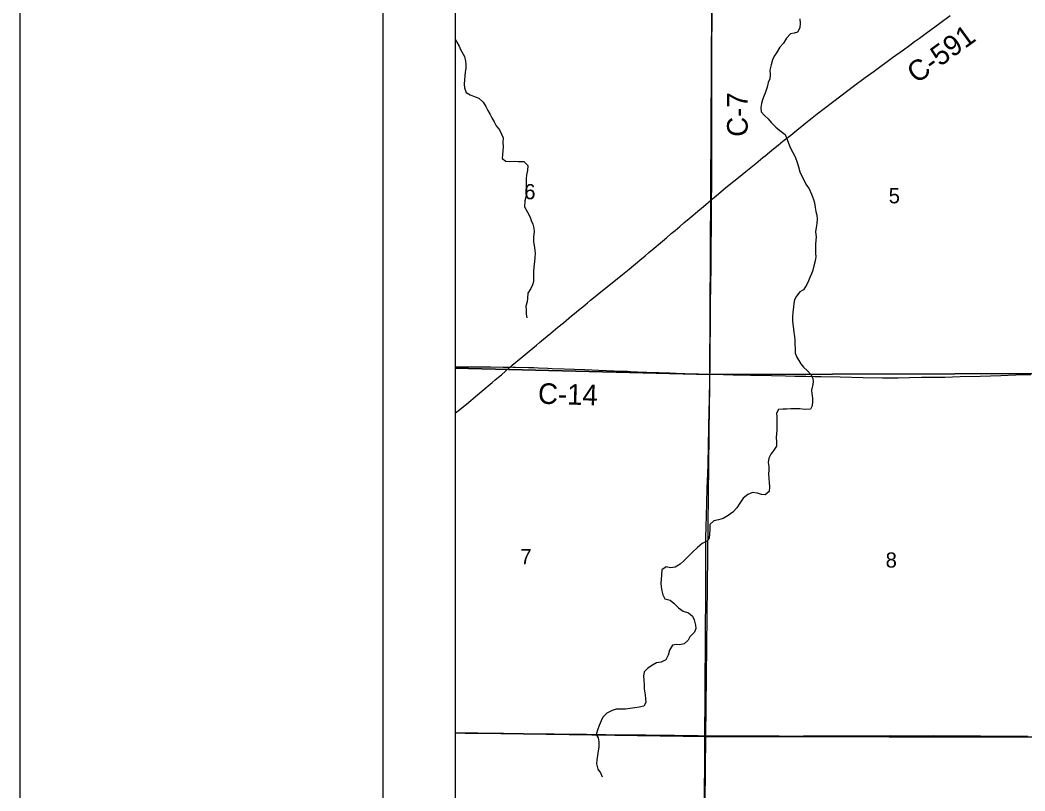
# Model space of a CAD drawing. Extents: x 0 to 34, y 0 to 22.
# Drawn here: x 2 to 3.385, y 16.332 to 17.395 of the extents above; entities that cross this region are included whole.
import ezdxf

# ---------------------------------------------------------------- set-up
doc = ezdxf.new("R2010")
doc.units = 0
for name, color, linetype in [('GM_X_County', 7, 'Continuous'), ('GM_X_County_Road', 7, 'Continuous'), ('GM_X_County_Road_Text', 7, 'Continuous'), ('GM_X_Minor_River', 7, 'Continuous'), ('GM_X_Section', 7, 'Continuous'), ('GM_X_Section_Text', 7, 'Continuous'), ('GM_X_Township', 7, 'Continuous'), ('GM_X_Township_Road', 7, 'Continuous'), ('SH_Border', 7, 'Continuous'), ('SH_Data', 7, 'Continuous')]:
    doc.layers.add(name, color=color, linetype=linetype)

msp = doc.modelspace()

# ---------------------------------------------------------------- linework, layer by layer
at = {"layer": 'GM_X_County'}
msp.add_lwpolyline([(9.4, 14.3965), (9.4, 20.9), (2.6, 20.9), (2.6, 14.4092)], dxfattribs=at)
at = {"layer": 'GM_X_County_Road'}
for points in [[(2.9535, 17.1477), (2.9535, 17.1515), (2.9536, 17.163), (2.9537, 17.1801), (2.9538, 17.1919), (2.9538, 17.2311), (2.9538, 17.264), (2.9538, 17.2836), (2.9539, 17.3181), (2.9539, 17.3355), (2.954, 17.3532), (2.9543, 17.4048), (2.9546, 17.4107), (2.9549, 17.4148)], [(2.9535, 17.1477), (2.9571, 17.1507), (2.963, 17.1558), (2.9699, 17.1616), (2.9756, 17.1663), (2.9841, 17.1732), (2.9882, 17.1765), (2.9955, 17.1823), (3.0006, 17.1864), (3.0074, 17.1918), (3.0146, 17.1977), (3.0242, 17.2056), (3.0271, 17.208), (3.0334, 17.213), (3.0389, 17.2176), (3.0454, 17.2229), (3.0519, 17.2282), (3.0625, 17.2368), (3.071, 17.2436), (3.0807, 17.2514), (3.0836, 17.2538), (3.088, 17.2572), (3.0919, 17.2603), (3.099, 17.2658), (3.1085, 17.2733), (3.1219, 17.2835), (3.1492, 17.304), (3.1654, 17.3162), (3.1774, 17.325), (3.2028, 17.3435), (3.2179, 17.3544), (3.2267, 17.3608), (3.2334, 17.3658), (3.24, 17.3705), (3.2492, 17.3774), (3.2683, 17.3913), (3.2822, 17.4016)], [(2.6762, 16.9169), (2.6787, 16.9192), (2.6911, 16.9296), (2.6992, 16.9364), (2.7071, 16.943), (2.7121, 16.9471), (2.7161, 16.9505), (2.7216, 16.9551), (2.7319, 16.9637), (2.7415, 16.9716), (2.7491, 16.9779), (2.7603, 16.9873), (2.7644, 16.9907), (2.77, 16.9952), (2.7757, 16.9999), (2.7822, 17.0053), (2.7867, 17.009), (2.793, 17.0141), (2.7983, 17.0185), (2.8162, 17.0329), (2.8305, 17.0444), (2.8396, 17.0518), (2.8545, 17.0641), (2.8619, 17.0703), (2.8671, 17.0747), (2.8743, 17.0807), (2.8828, 17.0879), (2.8911, 17.095), (2.8979, 17.1008), (2.9031, 17.1053), (2.9095, 17.1107), (2.9152, 17.1155), (2.9223, 17.1215), (2.928, 17.1263), (2.9347, 17.1319), (2.9395, 17.1359), (2.9457, 17.1411), (2.9514, 17.1459), (2.9535, 17.1477)], [(2.6, 16.8531), (2.6023, 16.855), (2.6153, 16.8657), (2.6305, 16.8785), (2.6365, 16.8835), (2.6511, 16.8956), (2.6551, 16.899), (2.6596, 16.9028), (2.6636, 16.9062), (2.6745, 16.9155), (2.6762, 16.9169)], [(2.6762, 16.9169), (2.6794, 16.9168), (2.683, 16.9168), (2.701, 16.9162), (2.7041, 16.9162), (2.7082, 16.916), (2.7141, 16.9158), (2.7277, 16.9152), (2.7336, 16.9149), (2.7501, 16.9143), (2.7787, 16.9133), (2.7982, 16.9125), (2.8193, 16.9117), (2.8377, 16.911), (2.8417, 16.9108), (2.8513, 16.9104), (2.8641, 16.9099), (2.8805, 16.9094), (2.8954, 16.9088), (2.914, 16.908), (2.9165, 16.9079), (2.9237, 16.9076), (2.9349, 16.9073), (2.9512, 16.9068)], [(2.9512, 16.9068), (2.9535, 16.9068), (2.97, 16.9064), (2.9833, 16.9061), (3.0072, 16.9057), (3.0209, 16.9054), (3.0361, 16.905), (3.0554, 16.9047), (3.0684, 16.9044), (3.0834, 16.9042), (3.0958, 16.9039), (3.1045, 16.9037), (3.1309, 16.9032), (3.1623, 16.9025), (3.189, 16.9021), (3.1983, 16.902), (3.2108, 16.9021), (3.2263, 16.9023), (3.2428, 16.9026), (3.263, 16.9028), (3.2751, 16.903), (3.2962, 16.9037), (3.3239, 16.9043), (3.3381, 16.9046), (3.3524, 16.9051), (3.3729, 16.906), (3.3934, 16.9067)]]:
    msp.add_lwpolyline(points, dxfattribs=at)
at = {"layer": 'GM_X_Minor_River'}
for points in [[(3.0751, 17.397), (3.0755, 17.3913), (3.0751, 17.3846), (3.0721, 17.3786), (3.0672, 17.3774), (3.0621, 17.3765), (3.0566, 17.3702), (3.0526, 17.3636), (3.0477, 17.3579), (3.0428, 17.3503), (3.0398, 17.3456), (3.0375, 17.3404), (3.0354, 17.3334), (3.0339, 17.3264), (3.0341, 17.3203), (3.0337, 17.3141), (3.0316, 17.3092), (3.0299, 17.3027), (3.028, 17.2961), (3.0258, 17.2913), (3.0235, 17.2853), (3.0224, 17.2805), (3.0212, 17.2747), (3.022, 17.269), (3.0263, 17.2635), (3.0316, 17.2589), (3.0354, 17.2542), (3.0418, 17.2476), (3.0477, 17.2432), (3.0547, 17.2373), (3.0577, 17.2307), (3.0594, 17.2256), (3.0621, 17.2187), (3.0653, 17.2125), (3.0685, 17.2066), (3.0715, 17.199), (3.0731, 17.1928), (3.0749, 17.1861), (3.0772, 17.181), (3.081, 17.1742), (3.0836, 17.1689), (3.0878, 17.1626), (3.0912, 17.1552), (3.094, 17.148), (3.0954, 17.1431), (3.0963, 17.1367), (3.0973, 17.1312), (3.0984, 17.1264), (3.0988, 17.1206), (3.0986, 17.1147), (3.0978, 17.1092), (3.0969, 17.1031), (3.0975, 17.0965), (3.0973, 17.0914), (3.0969, 17.0863), (3.0967, 17.0796), (3.0967, 17.0737), (3.0971, 17.069), (3.0961, 17.0631), (3.0944, 17.0563), (3.0931, 17.0504), (3.091, 17.0453), (3.0887, 17.0404), (3.087, 17.0356), (3.0846, 17.0307), (3.0804, 17.0235), (3.0753, 17.0203)], [(2.6, 17.3696), (2.6021, 17.3648), (2.6052, 17.3595), (2.6074, 17.3547), (2.6127, 17.3452), (2.6141, 17.3386), (2.6146, 17.3339), (2.6144, 17.3286), (2.6135, 17.3236), (2.6131, 17.3185), (2.6127, 17.313), (2.6125, 17.3069), (2.6127, 17.3018), (2.615, 17.2954), (2.6207, 17.2922), (2.6273, 17.2893), (2.6326, 17.2876), (2.6386, 17.2819), (2.6422, 17.2761), (2.6451, 17.2704), (2.6481, 17.2653), (2.6504, 17.2603), (2.6538, 17.2552), (2.6562, 17.2497), (2.6608, 17.2438), (2.6636, 17.2381), (2.6659, 17.2327), (2.6657, 17.2266), (2.6661, 17.2205), (2.6657, 17.2148), (2.6651, 17.2099), (2.6647, 17.2044), (2.6697, 17.2006), (2.675, 17.2002), (2.682, 17.2006), (2.6869, 17.2004), (2.6944, 17.2001), (2.7001, 17.1947), (2.6994, 17.1879), (2.6984, 17.1819), (2.6978, 17.1762), (2.6977, 17.1697), (2.6978, 17.165), (2.6982, 17.1593), (2.698, 17.1529), (2.696, 17.1458), (2.6956, 17.1377), (2.6994, 17.1305), (2.7033, 17.1237), (2.7048, 17.1189), (2.7069, 17.114), (2.7082, 17.1083), (2.7086, 17.1036), (2.7079, 17.096), (2.7077, 17.0895), (2.7086, 17.0842), (2.7098, 17.0782), (2.7103, 17.0734), (2.7098, 17.0681), (2.7092, 17.0621), (2.7084, 17.055), (2.7079, 17.048), (2.7079, 17.0423), (2.7077, 17.0349), (2.7065, 17.03), (2.7041, 17.0253), (2.6999, 17.0186), (2.6994, 17.012), (2.6992, 17.0067), (2.6975, 17.0008), (2.6977, 16.9955), (2.698, 16.9896)], [(3.0753, 17.0203), (3.0704, 17.0144), (3.0678, 17.0097), (3.067, 17.0045), (3.0662, 16.9998), (3.0653, 16.9918), (3.0649, 16.9865), (3.0649, 16.981), (3.0655, 16.9761), (3.0662, 16.9693), (3.067, 16.9642), (3.0679, 16.959), (3.0683, 16.9532), (3.0683, 16.9473), (3.0685, 16.9426), (3.0689, 16.9359), (3.0708, 16.9306), (3.0736, 16.9259), (3.0766, 16.9211), (3.0804, 16.9164), (3.0859, 16.9117), (3.0904, 16.9064), (3.0929, 16.9014), (3.0937, 16.8961), (3.0925, 16.891), (3.091, 16.8851), (3.0918, 16.8804), (3.0925, 16.874), (3.0925, 16.8692), (3.092, 16.8635), (3.0899, 16.8586), (3.0821, 16.858), (3.0753, 16.859), (3.0691, 16.8593), (3.0628, 16.8592), (3.0566, 16.8586), (3.0517, 16.8586), (3.0456, 16.8582), (3.043, 16.8533), (3.0432, 16.848), (3.0432, 16.8351), (3.0433, 16.8298), (3.0428, 16.8245), (3.0426, 16.8197), (3.0428, 16.8135), (3.0428, 16.8076), (3.0392, 16.8021), (3.035, 16.7968), (3.0324, 16.7911), (3.0314, 16.7852), (3.0322, 16.7797), (3.0322, 16.7746), (3.0318, 16.7695), (3.0326, 16.763), (3.0328, 16.7577), (3.0333, 16.7517), (3.0329, 16.7452), (3.0275, 16.7405), (3.0222, 16.7412), (3.0169, 16.7429), (3.0099, 16.7439), (3.0032, 16.741), (2.9972, 16.7361), (2.9923, 16.7291), (2.9881, 16.7225), (2.9828, 16.7166), (2.9764, 16.7118), (2.9692, 16.7081), (2.9632, 16.706), (2.9565, 16.7046), (2.9511, 16.6995), (2.9509, 16.6933), (2.9507, 16.6864), (2.9499, 16.6811), (2.9473, 16.6764), (2.9406, 16.6734), (2.9338, 16.668), (2.9272, 16.6614), (2.921, 16.6553), (2.9153, 16.6497), (2.9102, 16.6447), (2.9034, 16.6409), (2.8968, 16.64), (2.8909, 16.6411), (2.8847, 16.6371), (2.8845, 16.6301), (2.8837, 16.6237), (2.8835, 16.6186), (2.8837, 16.6138), (2.8847, 16.6079), (2.886, 16.6024), (2.8888, 16.5969), (2.8964, 16.5954), (2.9015, 16.5909), (2.9076, 16.5848), (2.9144, 16.5803), (2.9215, 16.5776), (2.9272, 16.5731), (2.9293, 16.5681), (2.9312, 16.5609), (2.9316, 16.556)], [(2.698, 16.9896), (2.6988, 16.9847)], [(2.9316, 16.556), (2.9299, 16.5511), (2.9236, 16.5448), (2.9212, 16.5401), (2.9157, 16.5348), (2.9098, 16.5338), (2.9049, 16.534), (2.8994, 16.5333), (2.8954, 16.5262), (2.8934, 16.5192), (2.8903, 16.513), (2.8841, 16.5099), (2.8777, 16.5088), (2.872, 16.5054), (2.8656, 16.5016), (2.8603, 16.4963), (2.8597, 16.4902), (2.8599, 16.4849), (2.8607, 16.4785), (2.8607, 16.4728), (2.8618, 16.4648), (2.8622, 16.4593), (2.8629, 16.454), (2.8599, 16.4489), (2.8537, 16.4477), (2.8476, 16.4468), (2.841, 16.446), (2.8347, 16.4451), (2.827, 16.4447), (2.8219, 16.4447), (2.8162, 16.4432), (2.8088, 16.4394), (2.8035, 16.4341), (2.8013, 16.4288), (2.7984, 16.4223), (2.796, 16.4161), (2.7941, 16.41), (2.7971, 16.4053), (2.7981, 16.3998), (2.7981, 16.3927), (2.7971, 16.3876), (2.796, 16.3808), (2.7952, 16.3751), (2.7947, 16.3694), (2.7964, 16.3622), (2.8001, 16.3573), (2.8026, 16.3514)]]:
    msp.add_lwpolyline(points, dxfattribs=at)
at = {"layer": 'GM_X_Section'}
for p, q in [((2.6, 17.4194), (2.6, 16.9153)), ((2.6, 16.9153), (2.6, 16.4121)), ((2.6, 16.4121), (2.6, 15.9095))]:
    msp.add_line(p, q, dxfattribs=at)
for points in [[(2.6, 16.9153), (2.9508, 16.9064), (2.9539, 17.4153), (2.6, 17.4194)], [(2.6, 16.4121), (2.9456, 16.4074), (2.9508, 16.9064), (2.6, 16.9153)], [(2.6, 15.9095), (2.9405, 15.9076), (2.9456, 16.4074), (2.6, 16.4121)]]:
    msp.add_lwpolyline(points, dxfattribs=at)
for points in [[(2.9539, 17.4153), (2.9558, 17.4152), (3.4597, 17.4098), (3.458, 16.9079), (2.9508, 16.9064)], [(2.9508, 16.9064), (3.458, 16.9079), (3.4505, 16.4063), (2.9456, 16.4074)], [(2.9456, 16.4074), (3.4505, 16.4063), (3.4449, 15.9065), (2.9405, 15.9076)]]:
    msp.add_lwpolyline(points, close=True, dxfattribs=at)
at = {"layer": 'GM_X_Township'}
msp.add_line((2.6, 17.4175), (2.6, 14.4092), dxfattribs=at)
at = {"layer": 'GM_X_Township_Road'}
for points in [[(2.9512, 16.9068), (2.9513, 16.9101), (2.9517, 16.9461), (2.9519, 16.9704), (2.9521, 16.9999), (2.9525, 17.0329), (2.9527, 17.0512), (2.953, 17.0689), (2.953, 17.0885), (2.9531, 17.1034), (2.9532, 17.1177), (2.9533, 17.1407), (2.9535, 17.1477)], [(2.6, 16.9171), (2.6056, 16.9171), (2.6485, 16.9169), (2.6659, 16.9167), (2.6706, 16.9166), (2.673, 16.9167), (2.6762, 16.9169)], [(2.9442, 16.4083), (2.9442, 16.4179), (2.9445, 16.4514), (2.9446, 16.4688), (2.9447, 16.4953), (2.9449, 16.5217), (2.945, 16.544), (2.9452, 16.5627), (2.9453, 16.5904), (2.9454, 16.6059), (2.9455, 16.6155), (2.9456, 16.6292), (2.9455, 16.6503), (2.9455, 16.6637), (2.9457, 16.6802), (2.9459, 16.6973), (2.9463, 16.7112), (2.947, 16.7293), (2.9475, 16.7498), (2.9482, 16.7696), (2.9486, 16.7833), (2.9491, 16.8082), (2.9502, 16.8576), (2.9508, 16.8809), (2.9511, 16.8998), (2.9512, 16.9068)], [(2.6, 16.4122), (2.6135, 16.412), (2.6274, 16.4119), (2.6386, 16.4118), (2.6542, 16.4117), (2.6663, 16.4116), (2.6849, 16.4113), (2.6958, 16.4111), (2.7182, 16.411), (2.7365, 16.4107), (2.781, 16.4102), (2.8074, 16.41), (2.8419, 16.4097), (2.8627, 16.4095), (2.8836, 16.4091), (2.9022, 16.409), (2.9215, 16.4086), (2.9349, 16.4085), (2.9442, 16.4083)], [(2.9417, 16.1569), (2.9418, 16.1608), (2.9422, 16.1885), (2.9423, 16.2028), (2.9424, 16.2155), (2.9425, 16.2342), (2.9429, 16.2684), (2.9433, 16.3047), (2.9436, 16.3361), (2.944, 16.3638), (2.9442, 16.3834), (2.9442, 16.4064), (2.9442, 16.4083)], [(2.9442, 16.4083), (2.9451, 16.4083), (2.9613, 16.4081), (2.9753, 16.408), (2.997, 16.408), (3.0147, 16.408), (3.0281, 16.4081), (3.0464, 16.408), (3.0673, 16.4078), (3.0803, 16.4079), (3.0974, 16.408), (3.1167, 16.4082), (3.1304, 16.4082), (3.1627, 16.4082), (3.186, 16.4083), (3.2003, 16.4084), (3.2227, 16.4083), (3.2413, 16.4083), (3.2594, 16.4084), (3.2774, 16.4082), (3.3016, 16.4082), (3.3243, 16.4082), (3.3616, 16.4078), (3.3734, 16.4077), (3.3831, 16.4076), (3.3896, 16.4076)]]:
    msp.add_lwpolyline(points, dxfattribs=at)
at = {"layer": 'SH_Border'}
msp.add_lwpolyline([(2, 21.5), (33.5, 21.5), (33.5, 0.5), (2, 0.5)], close=True, dxfattribs=at)
at = {"layer": 'SH_Data'}
for p, q in [((2.5, 21), (2.5, 14)), ((2.6, 20.9), (2.6, 14.1))]:
    msp.add_line(p, q, dxfattribs=at)

# ---------------------------------------------------------------- texts
at = {"layer": 'GM_X_County_Road_Text'}
for s, rotation, p in [('C-591', 36.0473, (3.2361, 17.3069)), ('C-7', 90, (3.0032, 17.2344)), ('C-14', 358.2856, (2.7138, 16.8663))]:
    msp.add_text(s, height=0.02841, rotation=rotation, dxfattribs=at).set_placement(p)
at = {"layer": 'GM_X_Section_Text'}
for s, p in [('6', (2.6951, 17.1482)), ('5', (3.1976, 17.1426)), ('7', (2.6897, 16.6447)), ('8', (3.1934, 16.6402))]:
    msp.add_text(s, height=0.0209, rotation=0, dxfattribs=at).set_placement(p)

doc.saveas('drawing.dxf')
